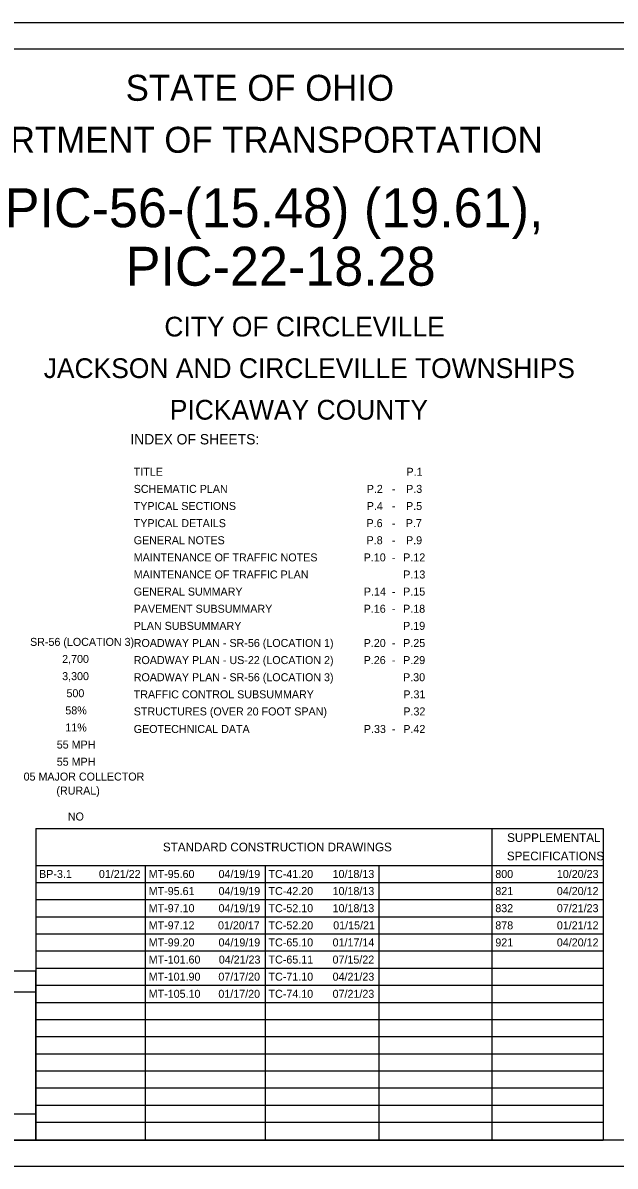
# Model space of a CAD drawing. Extents: x 0 to 34, y 0 to 22.
# Drawn here: x 11.82 to 23.21, y 0 to 22 of the extents above; entities that cross this region are included whole.
import ezdxf

# ---------------------------------------------------------------- set-up
doc = ezdxf.new("R2010")
doc.units = 0
for name, color, linetype in [('SH_Border', 7, 'Continuous'), ('SH_Cut_Line', 7, 'Continuous'), ('SH_Data', 7, 'Continuous'), ('SH_Text', 7, 'Continuous')]:
    doc.layers.add(name, color=color, linetype=linetype)

msp = doc.modelspace()

# ---------------------------------------------------------------- linework, layer by layer
at = {"layer": 'SH_Border'}
msp.add_lwpolyline([(1.5, 21.5), (33.5, 21.5), (33.5, 0.5), (1.5, 0.5)], close=True, dxfattribs=at)
at = {"layer": 'SH_Cut_Line'}
msp.add_lwpolyline([(0, 0), (34, 0), (34, 22), (0, 22)], close=True, dxfattribs=at)
at = {"layer": 'SH_Data'}
for p, q in [((12.064, 3.75), (9.264, 3.75)), ((12.064, 3.75), (12.064, 0.5)), ((12.064, 0.5), (12.064, 3.75)), ((12.064, 0.5), (12.064, 3.75)), ((12.064, 3.35), (9.264, 3.35)), ((9.264, 0.5), (12.064, 0.5)), ((12.064, 0.5), (9.264, 0.5)), ((12.064, 0.5), (9.264, 0.5))]:
    msp.add_line(p, q, dxfattribs=at)
msp.add_lwpolyline([(12.064, 0.5), (12.064, 1), (9.264, 1), (9.264, 0.5)], close=True, dxfattribs=at)
at = {"layer": 'SH_Text'}
for p, q in [((12.064, 6.495), (22.984, 6.495)), ((12.064, 6.495), (12.064, 0.5)), ((20.842, 6.495), (20.842, 0.5)), ((22.984, 6.495), (22.984, 0.5)), ((12.064, 5.787), (22.984, 5.787)), ((14.172, 5.787), (14.172, 0.5)), ((16.478, 5.787), (16.478, 0.5)), ((18.668, 5.787), (18.668, 0.5)), ((12.064, 5.458), (22.984, 5.458)), ((12.064, 5.128), (22.984, 5.128)), ((12.064, 4.799), (22.984, 4.799)), ((12.064, 4.469), (22.984, 4.469)), ((12.064, 4.14), (22.984, 4.14)), ((12.064, 3.811), (22.984, 3.811)), ((12.064, 3.481), (22.984, 3.481)), ((12.064, 3.152), (22.984, 3.152)), ((12.064, 2.822), (22.984, 2.822)), ((12.064, 2.493), (22.984, 2.493)), ((12.064, 2.164), (22.984, 2.164)), ((12.064, 1.834), (22.984, 1.834)), ((12.064, 1.505), (22.984, 1.505)), ((12.064, 1.175), (22.984, 1.175)), ((12.064, 0.846), (22.984, 0.846)), ((12.064, 0.5), (22.984, 0.5))]:
    msp.add_line(p, q, dxfattribs=at)

# ---------------------------------------------------------------- texts
for s, height, p in [('STATE OF OHIO', 0.5, (13.795, 20.5)), ('DEPARTMENT OF TRANSPORTATION', 0.5, (9.747, 19.5)), ('PIC-56-(15.48) (19.61),', 0.75, (11.467, 18.067)), ('PIC-22-18.28', 0.75, (13.795, 16.942)), ('CITY OF CIRCLEVILLE', 0.38, (14.54, 15.965)), ('JACKSON AND CIRCLEVILLE TOWNSHIPS', 0.38, (12.218, 15.165)), ('PICKAWAY COUNTY', 0.38, (14.644, 14.365)), ('INDEX OF SHEETS:', 0.2, (13.884, 13.888)), ('TITLE', 0.154, (13.95, 13.284)), ('P.1', 0.154, (19.198, 13.284)), ('SCHEMATIC PLAN', 0.154, (13.95, 12.955)), ('P.2', 0.154, (18.434, 12.955)), ('-', 0.154, (18.918, 12.955)), ('P.3', 0.154, (19.192, 12.955)), ('TYPICAL SECTIONS', 0.154, (13.95, 12.626)), ('P.4', 0.154, (18.434, 12.626)), ('P.5', 0.154, (19.19, 12.626)), ('-', 0.154, (18.918, 12.626)), ('TYPICAL DETAILS', 0.154, (13.95, 12.296)), ('P.6', 0.154, (18.43, 12.296)), ('-', 0.154, (18.918, 12.296)), ('P.7', 0.154, (19.185, 12.296)), ('GENERAL NOTES', 0.154, (13.95, 11.967)), ('P.8', 0.154, (18.431, 11.967)), ('P.9', 0.154, (19.19, 11.967)), ('-', 0.154, (18.918, 11.967)), ('MAINTENANCE OF TRAFFIC NOTES', 0.154, (13.95, 11.637)), ('P.10', 0.154, (18.375, 11.637)), ('-', 0.154, (18.918, 11.637)), ('P.12', 0.154, (19.136, 11.637)), ('MAINTENANCE OF TRAFFIC PLAN', 0.154, (13.95, 11.308)), ('P.13', 0.154, (19.137, 11.308)), ('GENERAL SUMMARY', 0.154, (13.95, 10.979)), ('P.14', 0.154, (18.379, 10.979)), ('-', 0.154, (18.918, 10.979)), ('P.15', 0.154, (19.135, 10.979)), ('PAVEMENT SUBSUMMARY', 0.154, (13.95, 10.649)), ('P.16', 0.154, (18.375, 10.649)), ('P.18', 0.154, (19.134, 10.649)), ('-', 0.154, (18.918, 10.649)), ('PLAN SUBSUMMARY', 0.154, (13.95, 10.32)), ('P.19', 0.154, (19.134, 10.32)), ('SR-56 (LOCATION 3)', 0.154, (11.955, 10.011)), ('ROADWAY PLAN - SR-56 (LOCATION 1)', 0.154, (13.95, 9.99)), ('P.20', 0.154, (18.375, 9.99)), ('P.25', 0.154, (19.135, 9.99)), ('-', 0.154, (18.918, 9.99)), ('2,700', 0.154, (12.573, 9.682)), ('ROADWAY PLAN - US-22 (LOCATION 2)', 0.154, (13.95, 9.661)), ('P.26', 0.154, (18.375, 9.661)), ('-', 0.154, (18.918, 9.661)), ('P.29', 0.154, (19.134, 9.661)), ('3,300', 0.154, (12.573, 9.352)), ('ROADWAY PLAN - SR-56 (LOCATION 3)', 0.154, (13.95, 9.331)), ('P.30', 0.154, (19.133, 9.331)), ('500', 0.154, (12.656, 9.023)), ('TRAFFIC CONTROL SUBSUMMARY', 0.154, (13.95, 9.002)), ('P.31', 0.154, (19.138, 9.002)), ('58%', 0.154, (12.634, 8.693)), ('STRUCTURES (OVER 20 FOOT SPAN)', 0.154, (13.95, 8.673)), ('P.32', 0.154, (19.138, 8.673)), ('11%', 0.154, (12.634, 8.364)), ('GEOTECHNICAL DATA', 0.154, (13.95, 8.335)), ('P.33', 0.154, (18.379, 8.335)), ('-', 0.154, (18.918, 8.335)), ('P.42', 0.154, (19.138, 8.335)), ('55 MPH', 0.154, (12.469, 8.035)), ('55 MPH', 0.154, (12.469, 7.705)), ('05 MAJOR COLLECTOR ', 0.154, (11.831, 7.419)), ('(RURAL)', 0.154, (12.462, 7.15)), ('NO', 0.154, (12.682, 6.651)), ('SUPPLEMENTAL', 0.168, (21.135, 6.238)), ('STANDARD CONSTRUCTION DRAWINGS', 0.168, (14.511, 6.057)), ('SPECIFICATIONS', 0.168, (21.13, 5.884)), ('BP-3.1', 0.154, (12.129, 5.545)), ('01/21/22', 0.154, (13.28, 5.545)), ('MT-95.60', 0.154, (14.238, 5.545)), ('04/19/19', 0.154, (15.582, 5.545)), ('TC-41.20', 0.154, (16.544, 5.545)), ('10/18/13', 0.154, (17.777, 5.545)), ('800', 0.154, (20.908, 5.545)), ('10/20/23', 0.154, (22.092, 5.545)), ('MT-95.61', 0.154, (14.238, 5.216)), ('04/19/19', 0.154, (15.582, 5.216)), ('TC-42.20', 0.154, (16.544, 5.216)), ('10/18/13', 0.154, (17.777, 5.216)), ('821', 0.154, (20.908, 5.216)), ('04/20/12', 0.154, (22.092, 5.216)), ('MT-97.10', 0.154, (14.238, 4.887)), ('04/19/19', 0.154, (15.582, 4.887)), ('TC-52.10', 0.154, (16.544, 4.887)), ('10/18/13', 0.154, (17.777, 4.887)), ('832', 0.154, (20.908, 4.887)), ('07/21/23', 0.154, (22.092, 4.887)), ('MT-97.12', 0.154, (14.238, 4.557)), ('01/20/17', 0.154, (15.572, 4.557)), ('TC-52.20', 0.154, (16.544, 4.557)), ('01/15/21', 0.154, (17.789, 4.557)), ('878', 0.154, (20.908, 4.557)), ('01/21/12', 0.154, (22.092, 4.557)), ('MT-99.20', 0.154, (14.238, 4.228)), ('04/19/19', 0.154, (15.582, 4.228)), ('TC-65.10', 0.154, (16.544, 4.228)), ('01/17/14', 0.154, (17.777, 4.228)), ('921', 0.154, (20.908, 4.228)), ('04/20/12', 0.154, (22.092, 4.228)), ('MT-101.60', 0.154, (14.238, 3.898)), ('04/21/23', 0.154, (15.587, 3.898)), ('TC-65.11', 0.154, (16.544, 3.898)), ('07/15/22', 0.154, (17.776, 3.898)), ('MT-101.90', 0.154, (14.238, 3.569)), ('07/17/20', 0.154, (15.579, 3.569)), ('TC-71.10', 0.154, (16.544, 3.569)), ('04/21/23', 0.154, (17.777, 3.569)), ('MT-105.10', 0.154, (14.238, 3.239)), ('01/17/20', 0.154, (15.579, 3.239)), ('TC-74.10', 0.154, (16.544, 3.239)), ('07/21/23', 0.154, (17.777, 3.239))]:
    msp.add_text(s, height=height, dxfattribs=at).set_placement(p)

doc.saveas('drawing.dxf')
